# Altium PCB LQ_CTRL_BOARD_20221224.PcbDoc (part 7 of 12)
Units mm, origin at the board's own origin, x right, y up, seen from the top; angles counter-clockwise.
Board outline 260 x 142 mm, 6 copper layers (Top Layer, Mid-Layer 1, Mid-Layer 2, Mid-Layer 3, Mid-Layer 4, Bottom Layer); 1105 components, 1039 nets, 3898 pads, 1277 vias.
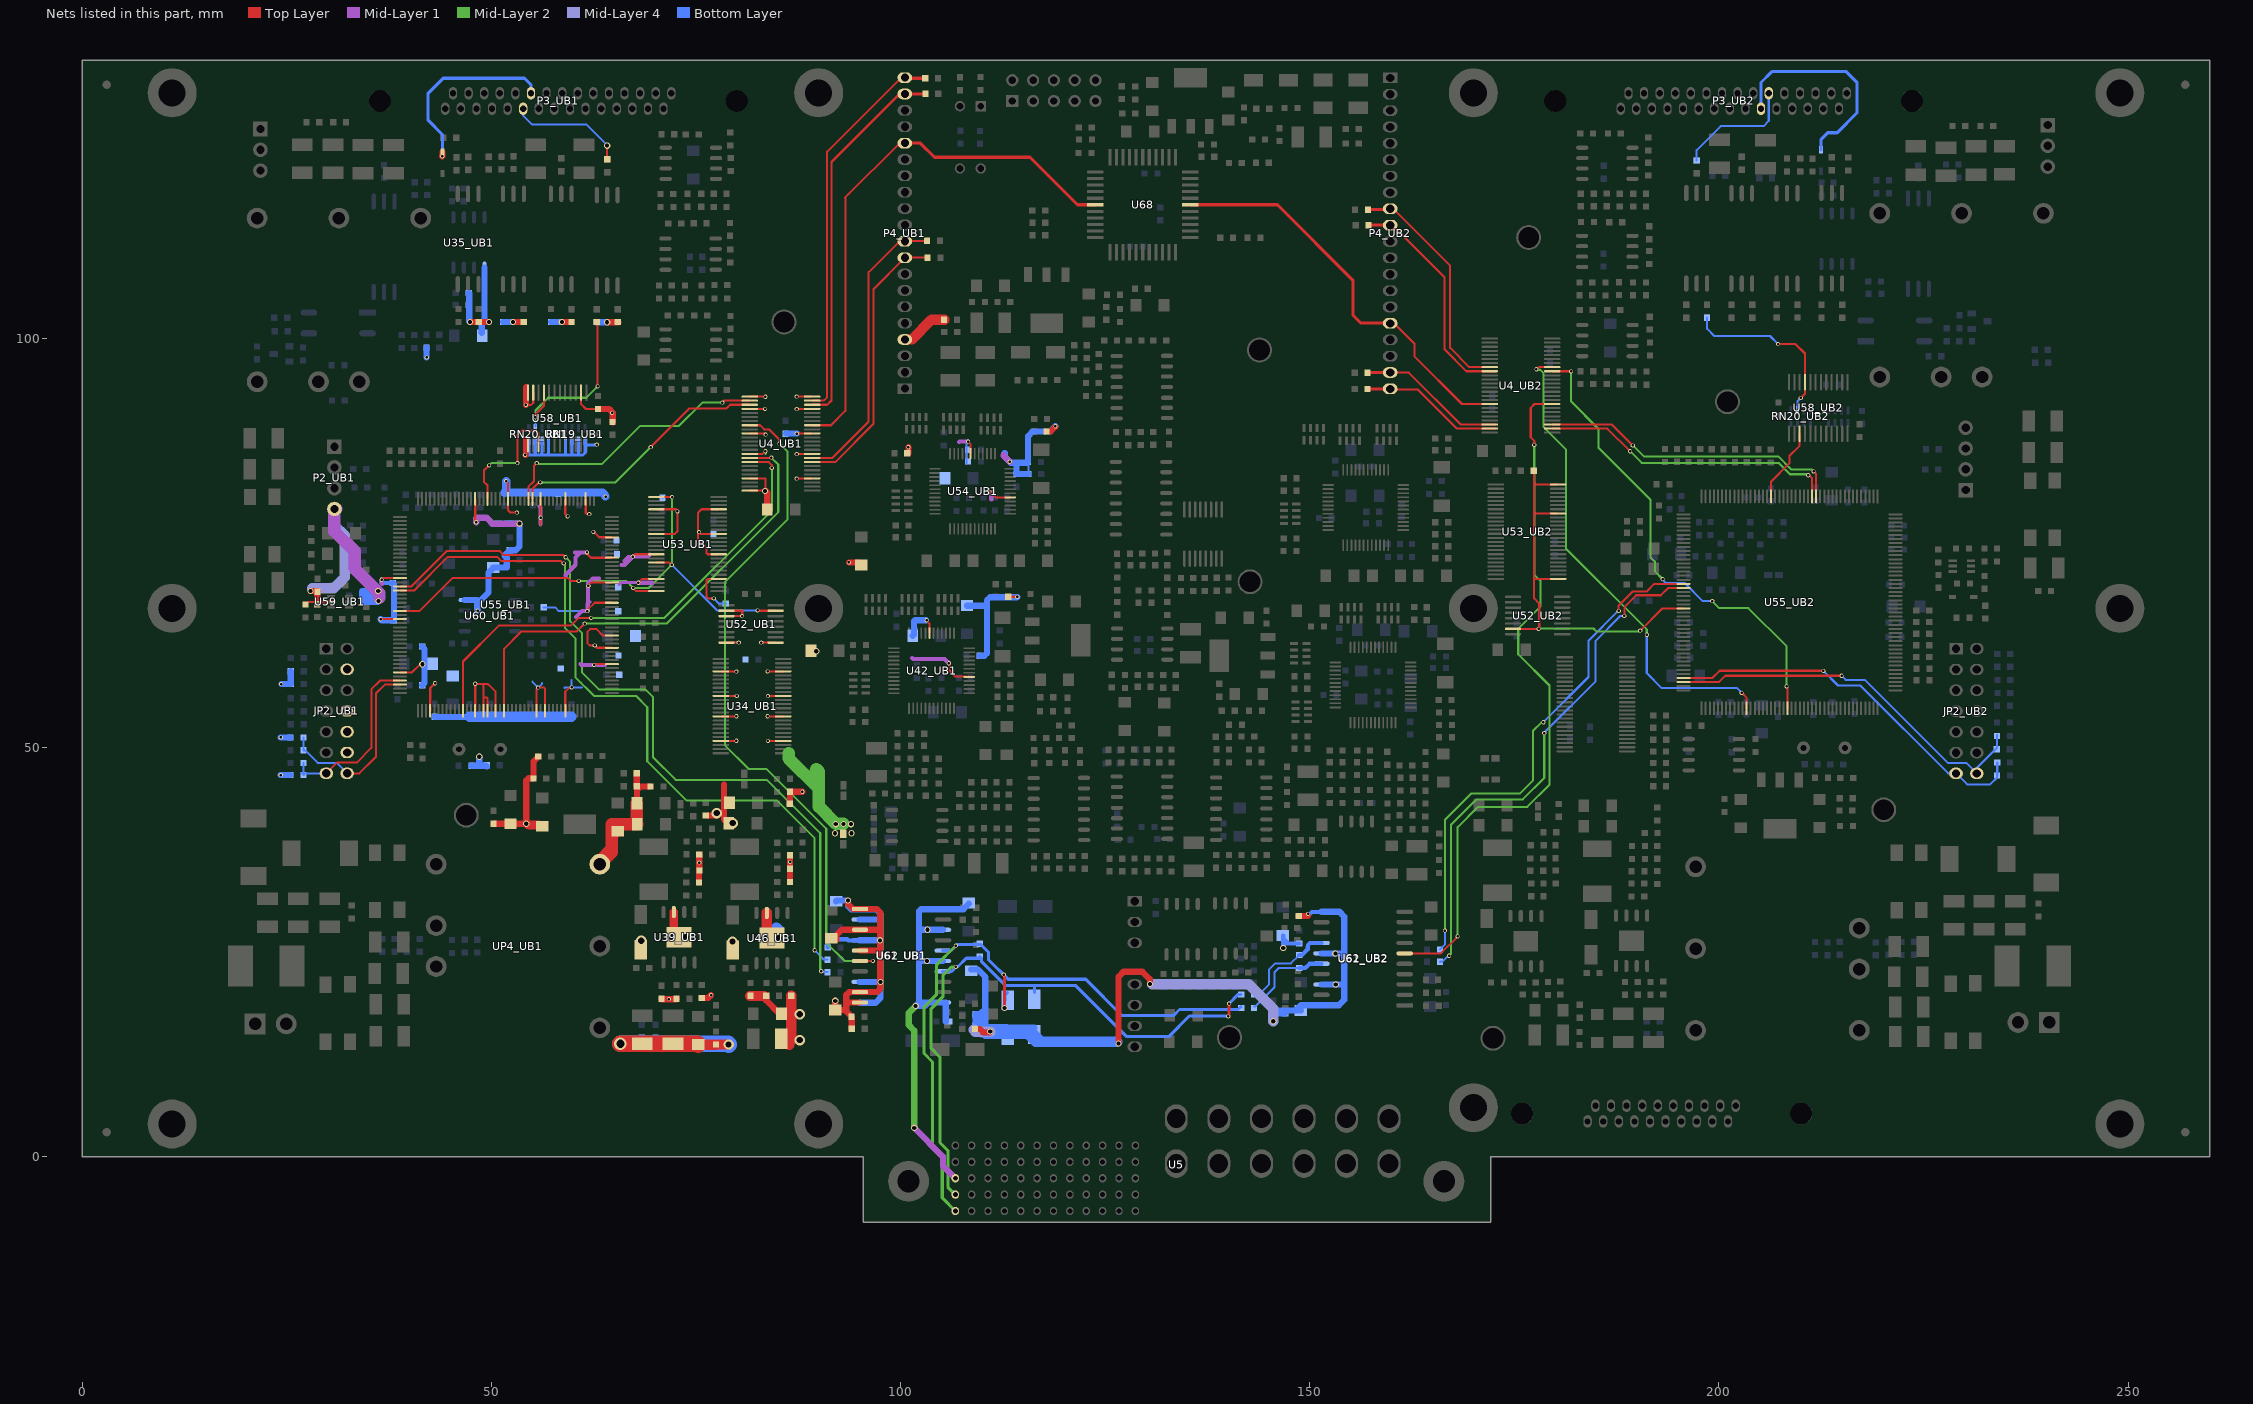
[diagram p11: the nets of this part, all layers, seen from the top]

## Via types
v1: diameter 0.508, hole 0.305, Top Layer to Bottom Layer, 845 vias
v2: diameter 0.762, hole 0.508, Top Layer to Bottom Layer, 317 vias
v3: diameter 1.27, hole 0.762, Top Layer to Bottom Layer, 77 vias
v4: diameter 2.032, hole 1.524, Top Layer to Bottom Layer, 15 vias
v5: diameter 2.032, hole 1.27, Top Layer to Bottom Layer, 11 vias
v6: diameter 1.27, hole 0.711, Top Layer to Bottom Layer, 8 vias
v7: diameter 2.54, hole 1.778, Top Layer to Bottom Layer, 3 vias
v8: diameter 1.524, hole 1.016, Top Layer to Bottom Layer, 1 vias

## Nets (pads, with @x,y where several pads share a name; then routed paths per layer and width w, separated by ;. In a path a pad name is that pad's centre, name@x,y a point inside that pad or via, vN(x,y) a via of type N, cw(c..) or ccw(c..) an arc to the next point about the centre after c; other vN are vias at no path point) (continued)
BRDC_CS_UB1: R313_UB1.1 U52_UB1.15 U53_UB1.25 U53_UB1.41 U53_UB1.48 U55_UB1.68 | length 67.9
  Top Layer w0.254: U55_UB1.68@38.84,66.691 41.24,66.691 45.288,70.739 59.334,70.739 59.715,70.358 v1(60.681,70.358) ; v1(67.335,69.494) 67.716,69.113 U53_UB1.48@69.367,69.113 ; U53_UB1.48@70.18,69.113 U53_UB1.48@70.993,69.113 ; U53_UB1.41@70.18,72.613 71.76,72.613 v1(72.06,72.314) ; U53_UB1.25@70.18,80.613 72.078,80.613 v1(72.085,80.606) ; v1(82.55,66.751) 82.88,66.751 ; 82.921,66.711 U52_UB1.15@84.74,66.711
  Mid-Layer 2 w0.254: v1(60.681,70.358) 66.472,70.358 v1(67.335,69.494) 69.24,69.494 v1(72.06,72.314) 72.06,76.479 72.085,76.505 v1(72.085,80.606)
  Bottom Layer w0.254: R313_UB1.1@70.917,80.518 71.005,80.606 v1(72.085,80.606) ; v1(72.06,72.314) 77.622,66.751 v1(82.55,66.751)
BRDC_CS_UB2: R313_UB2.1 U52_UB2.15 U53_UB2.25 U53_UB2.41 U53_UB2.48 U55_UB2.68 | length 50.5
  Top Layer w0.254: U52_UB2.15@174.848,64.506 177.993,64.506 178.054,64.567 178.054,67.589 177.419,68.224 177.419,70.587 ; R313_UB2.1@177.394,83.591 177.419,83.566 177.419,82.144 ; U53_UB2.25@180.365,70.618 177.451,70.618 177.419,70.587 ; U53_UB2.41@180.365,78.618 177.439,78.618 177.419,78.638 ; U53_UB2.48@180.365,82.118 177.444,82.118 177.419,82.144 ; v1(190.398,64.287) 193.107,66.996 ; 193.116,66.996 U55_UB2.68@195.685,66.996 ; 177.419,70.587 177.419,78.638 ; 177.419,78.638 177.419,82.144
  Mid-Layer 2 w0.254: v1(177.978,64.491) 178.029,64.541 184.683,64.541 185.039,64.186 190.398,64.186 v1(190.398,64.287)
CANGND_UB1: C11_UB1.2 C11_UB2.2 C410_UB1.2 C410_UB2.2 C411_UB1.2 C411_UB2.2 C412_UB1.2 C412_UB2.2 DR9.1 DR10.1 R367_UB1.1 R367_UB2.1 R371_UB1.1 R371_UB2.1 U5.C1 U61_UB1.11 U61_UB1.13 U61_UB1.16 U61_UB1.20 U61_UB2.11 U61_UB2.13 U61_UB2.16 U61_UB2.20 | length 169.2
  Top Layer w0.762: R371_UB1.1@109.118,15.621 109.682,15.621 110.114,15.189 110.871,15.189 v2(110.973,15.291) ; v2(126.644,13.843) 126.644,21.996 127.254,22.606 129.565,22.606 130.48,21.692 v2(130.48,21.107) ; R371_UB2.1@148.666,29.413 149.682,29.413 149.708,29.439 v1@149.809,29.439
  Mid-Layer 1 w0.762: v2(101.676,3.531) 105.181,0.025 105.181,-1.109 U5.C1@106.7,-2.627
  Mid-Layer 2 w0.762: v2(101.676,3.531) 101.676,15.418 101,16.094 101,17.561 v2(101.854,18.415)
  Mid-Layer 4 w1.27: 108.941,15.494 109.144,15.291 v2(110.973,15.291) ; v2@130.759,21.082 142.57,21.082 145.542,18.11 v2(145.542,16.561)
  Bottom Layer w0.508: v2@146.736,25.578 C11_UB2.2@146.736,27.051 C11_UB2.2@146.761,27.026 ; v2(146.761,25.502) v2@146.761,25.857 ; 147.726,26.06 R367_UB2.1@148.717,26.06 ; v1(149.809,29.667) 150.038,29.667 150.292,29.921 U61_UB2.20@151.449,29.921 ; v2@146.761,25.857 C11_UB2.2@146.761,27.026 ; v2@146.761,25.857 147.015,26.111 147.066,26.06 147.422,26.06 146.761,26.721 C11_UB2.2@146.761,27.026
  Bottom Layer w0.762: U61_UB1.16@105.161,23.927 102.286,23.927 102.26,23.952 ; U61_UB1.13@105.161,27.737 102.311,27.737 102.26,27.686 ; 105.537,16.535 105.537,18.847 U61_UB1.20@105.161,18.847 103.403,18.847 ; C11_UB1.2@108.356,30.912 107.696,30.251 U61_UB1.11@105.161,30.251 102.514,30.251 102.26,29.997 102.26,27.686 ; C411_UB1.2@108.636,22.885 109.449,22.885 110.363,21.971 110.363,17.851 ; C412_UB1.2@109.138,16.027 109.138,15.22 109.144,15.215 ; C412_UB1.2@109.164,16.053 C410_UB1.2@109.164,17.45 110.134,17.45 110.363,17.678 110.363,15.824 ; 110.261,15.189 110.363,15.291 110.363,15.824 ; DR9.1@116.357,15.748 113.055,15.748 112.979,15.824 110.363,15.824 ; v2@145.542,16.51 v2(145.542,16.561) 145.542,17.501 C412_UB2.2@145.567,17.526 ; C410_UB2.2@147.015,17.526 C412_UB2.2@145.567,17.526 ; C411_UB2.2@148.92,17.882 C411_UB2.2@148.299,17.882 ; U61_UB2.13@151.449,21.031 154.229,21.031 ; U61_UB2.16@151.449,24.841 154.203,24.841 154.229,24.867 ; U61_UB2.20@151.449,29.921 153.645,29.921 154.229,29.337 154.229,24.867 ; 102.26,18.821 102.286,18.847 103.403,18.847 ; 102.26,18.821 102.26,23.952 ; 102.26,18.821 v2(101.854,18.415) 102.972,18.415 103.403,18.847 ; 102.26,23.952 102.26,27.686 ; C412_UB2.2@145.567,17.526 145.923,17.882 C411_UB2.2@148.299,17.882 ; C411_UB2.2@148.299,17.882 148.934,18.517 U61_UB2.11@151.449,18.517 153.568,18.517 154.229,19.177 154.229,21.031 ; 154.229,21.031 154.229,24.867
  Bottom Layer w1.27: 110.134,17.45 109.823,17.139 109.823,15.316 109.95,15.189 110.261,15.189 110.414,15.037 115.545,15.037 116.51,14.072 117.221,14.072 ; DR9.1@116.357,14.935 117.221,14.072 ; v2@126.467,14.072 117.221,14.072
  other v2: 153.187,21.031 103.226,23.927 153.137,24.841 103.302,27.737
CANH_UB1: DR9.2 R370_UB1.1 R413.2 U5.B1 U61_UB1.17 | length 76.4
  Top Layer w0.381: v1(140.056,17.145) 140.157,17.247 v1(140.157,18.72)
  Mid-Layer 2 w0.381: U5.B1@106.7,-4.627 105.791,-3.718 105.791,0.762 104.826,1.727 104.826,12.167 103.746,13.246 103.746,18.098 105.181,19.533 105.181,22.149 106.223,23.19 v1(106.782,23.19)
  Bottom Layer w0.381: U61_UB1.17@105.161,22.657 106.248,22.657 v1(106.782,23.19) 106.832,23.241 107.036,23.241 108.052,24.257 ; 108.458,24.257 108.052,24.257 ; R370_UB1.1@109.677,24.46 R370_UB1.1@109.88,24.257 ; DR9.2@116.357,20.048 116.357,20.803 ; v1(140.056,17.145) 140.005,17.196 135.306,17.196 132.791,14.681 127.66,14.681 121.437,20.904 112.852,20.904 109.88,23.876 R370_UB1.1@109.88,24.257 ; v1(140.157,18.72) 141.275,19.837 R413.2@141.63,19.837 ; 108.052,24.257 R370_UB1.1@109.88,24.257
CANH_UB2: R370_UB2.1 R413.1 U61_UB2.17 | length 12.2
  Bottom Layer w0.254: R413.1@143.205,19.837 143.815,19.837 145.009,21.031 145.009,22.86 145.771,23.622 147.701,23.622 R370_UB2.1@148.717,24.638
  Bottom Layer w0.508: R370_UB2.1@148.717,24.638 149.047,24.638 149.758,25.349 149.758,25.654 149.784,25.679 149.784,25.857 150.038,26.111 U61_UB2.17@151.449,26.111
CANL_UB1: DR10.2 R370_UB1.2 R415.2 U5.A1 U61_UB1.15 | length 82.3
  Top Layer w0.381: v1(112.624,22.25) 112.725,22.149 v2(112.725,18.161)
  Mid-Layer 2 w0.381: U5.A1@106.7,-6.627 105.105,-5.032 105.105,0.102 103.911,1.295 103.911,11.582 102.87,12.624 102.87,18.263 104.383,19.776 104.383,23.408 v1(106.782,25.806)
  Bottom Layer w0.381: U61_UB1.15@105.161,25.197 106.223,25.197 106.959,25.933 109.83,25.933 110.744,25.019 110.744,24.105 113.157,21.692 122.631,21.692 127.076,17.247 133.35,17.247 134.087,17.983 141.249,17.983 R415.2@141.63,18.364 ; DR10.2@112.751,19.05 112.751,19.743 DR10.2@113.055,20.048
CANL_UB2: R370_UB2.2 R415.1 U61_UB2.15 | length 11.5
  Bottom Layer w0.254: R415.1@143.205,18.364 143.358,18.364 145.694,20.701 145.694,22.555 146.202,23.063 R370_UB2.2@148.717,23.063
  Bottom Layer w0.508: R370_UB2.2@148.717,23.063 149.454,23.063 149.962,23.571 U61_UB2.15@151.449,23.571
CANRXA_UB1: R368_UB1.2 U55_UB1.62 | length 98.9
  Top Layer w0.254: U55_UB1.62@38.84,69.691 40.252,69.691 44.577,74.016 51.02,74.016 51.528,73.508 58.826,73.508 v1(59.08,73.254)
  Mid-Layer 2 w0.254: v1@59.068,73.292 59.639,72.72 59.639,65.43 ; 59.639,67.183 59.639,65.43 ; 70.18,48.412 69.748,48.844 ; v1(90.322,22.657) 90.195,22.784 90.195,39.522 83.668,46.05 72.542,46.05 69.748,48.844 ; 59.639,65.43 61.062,64.008 61.062,59.182 63.144,57.099 68.834,57.099 69.748,56.185 69.748,48.844
  Bottom Layer w0.254: v1(90.322,22.657) 90.424,22.555 R368_UB1.2@91.084,22.555
CANRXA_UB2: R368_UB2.2 U55_UB2.62 | length 63.8
  Top Layer w0.254: v1(187.757,66.7) 187.757,67.361 189.459,69.063 191.186,69.063 192.119,69.996 U55_UB2.62@195.685,69.996
  Mid-Layer 2 w0.254: v1@166.497,27.61 v1(166.522,27.635) 166.522,41.148 169.774,44.399 175.717,44.399 177.267,45.949 177.267,52.019 178.346,53.099 v1(178.549,53.099)
  Bottom Layer w0.254: R368_UB2.2@165.913,25.298 166.522,25.908 v1(166.522,27.635) ; v1(178.549,53.099) 184.074,58.623 184.074,63.068 187.706,66.7 v1(187.757,66.7)
CANTXA_UB1: R369_UB1.2 U55_UB1.63 | length 94.5
  Top Layer w0.254: U55_UB1.63@38.84,69.191 40.591,69.191 44.704,73.304 50.724,73.304 51.232,72.796 58.496,72.796 v1@58.826,72.466
  Mid-Layer 2 w0.254: v1@58.826,72.466 59.03,72.263 59.03,64.592 ; 59.03,64.618 59.03,64.592 ; 60.935,57.937 60.274,58.598 ; v1@89.51,25.248 89.51,38.913 84.887,43.536 73.838,43.536 69.063,48.311 69.063,54.94 67.701,56.301 62.571,56.301 60.274,58.598 ; 59.03,64.592 60.274,63.348 60.274,58.598
  Bottom Layer w0.254: v1(89.51,25.222) 90.653,24.079 R369_UB1.2@91.084,24.079
  other v1: 58.852,72.492
CANTXA_UB2: R369_UB2.2 U55_UB2.63 | length 64.7
  Top Layer w0.254: v1(188.443,66.091) 188.443,67.14 189.908,68.605 192.913,68.605 193.803,69.496 U55_UB2.63@195.685,69.496
  Mid-Layer 2 w0.254: v1(167.03,24.562) 167.259,24.79 167.259,40.538 170.383,43.663 176.047,43.663 178.664,46.279 v1(178.664,51.765)
  Bottom Layer w0.254: R369_UB2.2@165.913,23.825 166.192,23.825 166.929,24.562 v1(167.03,24.562) ; v1(178.664,51.765) 178.638,51.791 184.937,58.09 184.937,63.043 187.985,66.091 v1(188.443,66.091)
EMU0_UB1: C375_UB1.1 JP2_UB1.13 R311_UB1.1 U55_UB1.85 | length 22.7
  Top Layer w0.254: JP2_UB1.13@29.845,46.849 31.142,48.146 33.541,48.146 35.357,49.962 35.357,57.099 36.449,58.191 U55_UB1.85@38.84,58.191
  Bottom Layer w0.254: C375_UB1.1@26.809,46.849 C375_UB1.1@27.266,46.849 ; R311_UB1.1@27.051,48.108 C375_UB1.1@27.051,46.634 C375_UB1.1@27.266,46.849 ; JP2_UB1.13@29.845,46.849 C375_UB1.1@27.266,46.849
EMU0_UB2: C375_UB2.1 JP2_UB2.13 R311_UB2.1 U55_UB2.85 | length 46.6
  Top Layer w0.254: U55_UB2.85@195.685,58.496 199.212,58.496 200.101,59.385 v1@212.801,59.385
  Bottom Layer w0.254: v1(212.776,59.36) 214.554,57.582 217.272,57.582 228.016,46.838 JP2_UB2.13@228.981,46.838 230.327,45.491 233.147,45.491 233.985,46.33 233.985,46.646 234.01,46.672 R311_UB2.1@234.01,48.17
EMU1_UB1: C376_UB1.1 JP2_UB1.14 R312_UB1.2 U55_UB1.86 | length 23.5
  Top Layer w0.254: JP2_UB1.14@32.385,46.849 33.87,46.849 35.916,48.895 35.916,56.617 36.99,57.691 U55_UB1.86@38.84,57.691
  Bottom Layer w0.254: C376_UB1.1@27.051,51.232 R312_UB1.2@27.051,49.657 27.254,49.657 28.778,48.133 31.101,48.133 JP2_UB1.14@32.385,46.849
EMU1_UB2: C376_UB2.1 JP2_UB2.14 R312_UB2.2 U55_UB2.86 | length 46.6
  Top Layer w0.254: U55_UB2.86@195.685,57.996 200.007,57.996 200.787,58.776 214.723,58.776
  Bottom Layer w0.254: v1(214.986,58.776) 215.494,58.268 217.843,58.268 227.978,48.133 230.226,48.133 JP2_UB2.14@231.521,46.838 231.521,47.498 233.959,49.936 233.959,51.523 C376_UB2.1@233.985,51.548
EN_TXD_UB1: P4_UB1.16 U4_UB1.17 U68.6 | length 68
  Top Layer w0.254: U4_UB1.17@89.205,89.382 91.515,89.382 93.269,91.135 93.269,117.221 ; 93.218,117.17 93.269,117.221 ; 93.701,117.653 93.269,117.221 ; P4_UB1.16@100.533,123.853 99.901,123.853 93.269,117.221
  Top Layer w0.381: P4_UB1.16@100.533,123.853 102.436,123.853 104.165,122.123 115.824,122.123 121.627,116.32 U68.6@123.8,116.32
EN_TXD_UB2: P4_UB2.16 U4_UB2.17 U68.28 | length 50.9
  Top Layer w0.254: P4_UB2.16@159.842,101.572 160.581,101.572 162.789,99.365 162.789,97.79 168.605,91.973 U4_UB2.17@172.771,91.973
  Top Layer w0.381: U68.28@135.4,116.32 146.062,116.32 155.27,107.112 155.27,102.845 156.235,101.879 159.535,101.879 P4_UB2.16@159.842,101.572
EN_WK_UB1: R23_UB1.1 RN20_UB1.3 U58_UB1.9 | length 22.2
  Top Layer w0.254: v1(55.397,90.348) 55.397,90.703 56.426,91.732 U58_UB1.9@56.426,93.37 ; v1(62.997,94.132) R23_UB1.1@62.997,102.083
  Mid-Layer 2 w0.254: v1(55.397,90.348) 55.397,91.186 56.947,92.735 61.6,92.735 v1(62.997,94.132)
  Bottom Layer w0.254: RN20_UB1.3@55.378,89.256 55.378,90.329 v1(55.397,90.348)
EN_WK_UB2: R23_UB2.1 RN20_UB2.3 U58_UB2.9 | length 21.9
  Top Layer w0.254: v1(207.239,99.289) 207.264,99.314 209.347,99.314 210.519,98.141 U58_UB2.9@210.519,94.64 210.519,93.222 v1(210.007,92.71)
  Bottom Layer w0.254: R23_UB2.1@198.557,102.514 198.557,101.163 199.441,100.279 206.248,100.279 v1(207.239,99.289) ; RN20_UB2.3@209.607,91.211 209.607,92.31 v1(210.007,92.71)
EN_WORK_UB1: U55_UB1.27 U58_UB1.15 | length 15.8
  Top Layer w0.254: U55_UB1.27@49.54,80.391 49.54,82.057 49.098,82.499 49.098,83.845 v1(49.733,84.48) ; v1(53.188,84.76) 53.188,88.239 53.696,88.748 55.397,88.748 55.776,88.369 U58_UB1.15@55.776,87.07
  Mid-Layer 2 w0.254: v1(49.733,84.48) 50.013,84.76 v1(53.188,84.76)
EN_WORK_UB2: U55_UB2.27 U58_UB2.15 | length 9.1
  Top Layer w0.254: U55_UB2.27@206.385,80.696 206.385,82.509 208.61,84.734 208.61,85.432 208.636,85.458 208.636,85.648 209.869,86.882 ; 209.869,86.868 U58_UB2.15@209.869,88.34
EN_WRK_UB1: P3_UB1.6 R248_UB1.2 | length 14.4
  Top Layer w0.254: R248_UB1.2@64.166,121.869 v2@64.166,123.546
  Bottom Layer w0.254: P3_UB1.6@53.899,128.047 53.899,127.203 54.966,126.136 61.62,126.136 64.033,123.723 v2@64.338,123.723
  other v2: 64.16,123.546
EN_WRK_UB2: P3_UB2.6 R248_UB2.2 | length 15.5
  Bottom Layer w0.254: R248_UB2.2@197.287,121.742 197.287,122.992 200.228,125.933 205.461,125.933 206.096,126.568 P3_UB2.6@206.096,130.505
ENA_TXD_UB1: U4_UB1.32 U62_UB1.6 | length 84
  Top Layer w0.254: U4_UB1.32@81.585,89.382 82.856,89.382 83.356,88.882 83.94,88.882 85.217,87.605 v1(85.217,87.147) ; U62_UB1.6@95.052,23.927 v1(96.622,23.927)
  Mid-Layer 2 w0.254: v1(85.217,87.147) 86.208,86.157 86.208,77.876 78.537,70.206 78.537,50.292 81.432,47.396 83.617,47.396 90.932,40.081 90.932,26.152 93.157,23.927 v1(96.622,23.927)
ENA_TXD_UB2: U4_UB2.32 U62_UB2.6 | length 86.2
  Top Layer w0.254: U62_UB2.6@161.615,24.841 166.014,24.841 168.072,26.899 v1(168.072,26.924) ; v1(177.444,86.97) 177.444,87.477 177.013,87.909 177.013,91.511 177.476,91.974 U4_UB2.32@179.629,91.974
  Top Layer w0.381: U62_UB2.6@161.615,24.841 U62_UB2.6@161.691,24.917
  Mid-Layer 2 w0.254: v1(168.072,26.924) 168.072,40.259 170.561,42.748 176.581,42.748 179.299,45.466 179.299,57.582 175.489,61.392 175.489,64.516 178.181,67.208 178.181,70.383 177.444,71.12 v1(177.444,86.97)
ET_IO_IN1_UB1: U4_UB1.27 U55_UB1.16 | length 32.1
  Top Layer w0.254: U55_UB1.16@55.04,80.391 55.04,81.622 55.74,82.321 55.982,82.321 v1(55.982,82.398) ; v1(69.494,86.716) 74.219,91.44 78.74,91.44 79.182,91.882 U4_UB1.27@81.585,91.882
  Mid-Layer 2 w0.254: v1(55.982,82.398) 65.176,82.398 v1(69.494,86.716)
ET_IO_IN1_UB2: U4_UB2.27 U55_UB2.16 | length 37.6
  Top Layer w0.254: U4_UB2.27@179.629,89.474 186.917,89.474 189.509,86.882 189.509,86.893 v1(189.484,86.919) ; v1(211.582,83.744) 211.885,83.441 U55_UB2.16@211.885,80.696
  Mid-Layer 2 w0.254: v1(189.484,86.919) 190.83,85.573 207.239,85.573 208.839,83.972 211.207,83.972 211.353,83.972 v1(211.582,83.744)
ET_IO_IN2_UB1: U4_UB1.26 U55_UB1.17 | length 34.1
  Top Layer w0.254: U55_UB1.17@54.54,80.391 54.54,81.845 55.22,82.525 55.22,84.43 v1(55.55,84.76) ; v1(78.232,92.151) 78.462,92.382 U4_UB1.26@81.585,92.382
  Mid-Layer 2 w0.254: v1(55.55,84.76) 55.651,84.658 63.551,84.658 68.192,89.3 72.942,89.3 75.794,92.151 v1(78.232,92.151)
ET_IO_IN2_UB2: U4_UB2.26 U55_UB2.17 | length 36.5
  Top Layer w0.254: U4_UB2.26@179.629,88.974 186.362,88.974 189.154,86.182 v1(189.154,86.208) ; v1@210.998,83.337 210.998,83.299 211.385,82.911 U55_UB2.17@211.385,80.696
  Mid-Layer 2 w0.254: v1@189.179,86.182 190.576,84.785 207.289,84.785 208.686,83.388 210.642,83.388 210.795,83.388 v1(210.922,83.261)
ET_IO_OUT1_UB1: U4_UB1.41 U55_UB1.100 | length 59.8
  Top Layer w0.254: U55_UB1.100@46.54,54.491 46.54,60.51 50.927,64.897 59.726,64.897 60.666,65.837 v1(62.205,65.837) ; U4_UB1.41@81.585,84.882 83.901,84.882 84.277,84.506 v1(84.277,84.176)
  Mid-Layer 2 w0.254: v1(62.205,65.837) 71.171,65.837 84.277,78.943 v1(84.277,84.176)
ET_IO_OUT1_UB2: U4_UB2.41 U55_UB2.100 | length 59.8
  Top Layer w0.254: v1(177.698,96.215) 177.788,96.215 178.047,96.474 U4_UB2.41@179.629,96.474 ; v1(202.768,56.667) 202.819,56.667 203.385,56.101 U55_UB2.100@203.385,54.796
  Mid-Layer 2 w0.254: v1(177.698,96.215) 177.749,96.164 178.156,96.164 178.587,95.733 178.587,89.154 181.305,86.436 181.305,74.32 191.186,64.44 v1@191.186,63.805
  Bottom Layer w0.254: v1@191.186,63.805 191.186,59.106 193.04,57.252 202.235,57.252 202.819,56.667 v1(202.768,56.667)
  other v1: 191.211,63.779
ET_IO_OUT2_UB1: U4_UB1.40 U55_UB1.110 | length 57.7
  Top Layer w0.254: U55_UB1.110@51.54,54.491 51.54,62.03 53.696,64.186 60.452,64.186 v1(61.417,65.151) ; U4_UB1.40@81.585,85.382 84.188,85.382 v1(84.226,85.42)
  Mid-Layer 2 w0.254: v1(61.417,65.151) 71.45,65.151 85.065,78.765 85.065,84.582 v1(84.226,85.42)
ET_IO_OUT2_UB2: U4_UB2.40 U55_UB2.110 | length 58.6
  Top Layer w0.254: U4_UB2.40@179.629,95.974 181.927,95.974 v1(181.94,95.961) ; v1(208.28,57.474) 208.385,57.369 U55_UB2.110@208.385,54.796
  Mid-Layer 2 w0.254: v1(181.94,95.961) 181.94,92.278 185.293,88.925 185.293,86.639 191.643,80.289 191.643,73.203 191.694,73.203 192.176,72.72 192.176,71.526 v1(193.116,70.587) ; v1(199.187,67.894) 200.05,67.031 203.606,67.031 208.28,62.357 v1(208.28,57.474)
  Bottom Layer w0.254: v1(193.116,70.587) 193.116,70.561 193.091,70.536 193.523,70.104 195.809,70.104 198.018,67.894 v1(199.187,67.894)
EXT_IO_IN1_UB1: P4_UB1.19 R391.1 U4_UB1.22 | length 46.9
  Top Layer w0.254: U4_UB1.22@89.205,91.882 91.043,91.882 91.567,92.405 91.567,121.539 ; 91.948,121.92 91.567,121.539 ; P4_UB1.19@100.533,129.853 99.881,129.853 91.567,121.539
  Top Layer w0.381: P4_UB1.19@100.533,129.853 102.76,129.853 R391.1@102.794,129.819
EXT_IO_IN1_UB2: P4_UB2.19 R432.1 U4_UB2.22 | length 18.4
  Top Layer w0.254: P4_UB2.19@159.605,95.809 162.128,95.809 168.463,89.474 U4_UB2.22@172.771,89.474
  Top Layer w0.381: R432.1@157.074,95.58 157.302,95.809 P4_UB2.19@159.605,95.809
EXT_IO_IN2_UB1: P4_UB1.20 R392.1 U4_UB1.23 | length 48
  Top Layer w0.254: U4_UB1.23@89.205,92.382 90.629,92.382 91.034,92.786 91.034,122.809 100.078,131.853 P4_UB1.20@100.533,131.853
  Top Layer w0.381: P4_UB1.20@100.533,131.853 100.611,131.775 R392.1@103.2,131.775
EXT_IO_IN2_UB2: P4_UB2.20 R433.1 U4_UB2.23 | length 17.8
  Top Layer w0.254: P4_UB2.20@160.022,93.751 163.22,93.751 167.997,88.974 U4_UB2.23@172.771,88.974
  Top Layer w0.381: R433.1@157.074,93.802 P4_UB2.20@159.793,93.802 ; P4_UB2.20@159.793,93.523 P4_UB2.20@160.022,93.751
EXT_IO_OUT1_UB1: P4_UB1.9 R393.1 U4_UB1.8 | length 34.1
  Top Layer w0.254: U4_UB1.8@89.205,84.882 92.008,84.882 96.698,89.571 96.698,106.018 P4_UB1.9@100.533,109.853 100.535,109.855 R393.1@103.302,109.855
EXT_IO_OUT1_UB2: P4_UB2.9 R434.1 U4_UB2.8 | length 29.6
  Top Layer w0.254: P4_UB2.9@160.146,115.876 167.157,108.864 167.157,98.831 169.514,96.474 U4_UB2.8@172.72,96.474
  Top Layer w0.381: R434.1@157.124,115.722 P4_UB2.9@159.84,115.722 ; P4_UB2.9@159.84,115.57 P4_UB2.9@160.146,115.876
EXT_IO_OUT2_UB1: P4_UB1.10 R394.1 U4_UB1.9 | length 35.7
  Top Layer w0.254: U4_UB1.9@89.205,85.382 91.655,85.382 96.114,89.84 96.114,108.077 99.89,111.853 P4_UB1.10@100.533,111.853 100.593,111.912 R394.1@103.251,111.912
EXT_IO_OUT2_UB2: P4_UB2.10 R436.1 U4_UB2.9 | length 28
  Top Layer w0.254: P4_UB2.10@159.842,113.572 160.367,113.572 166.472,107.467 166.472,98.654 169.151,95.974 U4_UB2.9@172.72,95.974
  Top Layer w0.381: R436.1@157.277,113.843 P4_UB2.10@159.876,113.843 ; P4_UB2.10@159.8,113.614 P4_UB2.10@159.842,113.572
FAULT_UB1: D16_UB1.2 P3_UB1.21 | length 23.6
  Top Layer w0.762: v1(44.018,122.25) D16_UB1.2@44.044,122.742
  Bottom Layer w0.381: v1@44.044,122.25 44.044,124.892 42.291,126.644 42.291,129.946 44.12,131.775 54.051,131.775 54.851,130.976 P3_UB1.21@54.851,129.952
FAULT_UB2: D16_UB2.2 P3_UB2.21 | length 29.5
  Bottom Layer w0.381: P3_UB2.21@205.146,128.047 205.146,131.257 206.477,132.588 ; 209.194,132.588 206.477,132.588 ; D16_UB2.2@212.496,123.021 212.496,124.307 213.309,125.12 214.452,125.12 216.865,127.533 216.865,131.293 215.57,132.588 206.477,132.588
GND_UB1: C10_UB1.2 C16_UB1.2 C17_UB1.2 C228_UB1.2 C233_UB1.2 C234_UB1.1 C235_UB1.1 C237_UB1.1 C238_UB1.1 C254_UB1.2 C255_UB1.2 C263_UB1.2 C264_UB1.1 C265_UB1.2 C266_UB1.1 C273_UB1.1 C274_UB1.1 C291_UB1.2 C292_UB1.2 C294_UB1.2 C295_UB1.1 C296_UB1.1 C297_UB1.1 C309_UB1.2 C310_UB1.1 C313_UB1.2 C314_UB1.2 C315_UB1.2 C316_UB1.2 C317_UB1.2 C318_UB1.2 C320_UB1.2 C321_UB1.2 C322_UB1.1 C323_UB1.1 C331_UB1.1 C332_UB1.1 C333_UB1.1 C334_UB1.1 C335_UB1.1 C336_UB1.1 C337_UB1.1 C338_UB1.1 C339_UB1.1 C340_UB1.1 C341_UB1.1 C342_UB1.1 C346_UB1.1 C347_UB1.1 C348_UB1.1 C349_UB1.1 C350_UB1.1 C351_UB1.1 C352_UB1.1 C353_UB1.1 C356_UB1.2 C357_UB1.2 C358_UB1.2 C359_UB1.2 C366_UB1.1 C367_UB1.2 C368_UB1.1 C375_UB1.2 C376_UB1.2 C383_UB1.2 C384_UB1.1 C385_UB1.2 C386_UB1.2 C387_UB1.2 C388_UB1.2 C390_UB1.1 C391_UB1.1 C401_UB1.2 C402_UB1.2 C403_UB1.2 C404_UB1.2 C405_UB1.1 C406_UB1.2 C407_UB1.2 C408_UB1.1 C409_UB1.2 C413_UB1.2 C414_UB1.2 C415_UB1.2 C416_UB1.2 C417_UB1.2 C418_UB1.2 C419_UB1.2 D20_UB1.1 D22_UB1.1 JP2_UB1.4 JP2_UB1.8 JP2_UB1.10 JP2_UB1.12 P2_UB1.4 P4_UB1.4 R1.1 R27_UB1.1 R210_UB1.1 R226_UB1.1 R227_UB1.1 R231_UB1.2 R234_UB1.2 R240_UB1.1 R241_UB1.1 R242_UB1.1 R243_UB1.2 R245_UB1.1 R247_UB1.1 R253_UB1.1 R254_UB1.1 R255_UB1.1 R262_UB1.2 R273_UB1.1 R274_UB1.2 R276_UB1.1 R289_UB1.1 R294_UB1.1 R296_UB1.2 R299_UB1.1 R302_UB1.1 R310_UB1.1 R359_UB1.2 R364_UB1.2 RN19_UB1.2 RN19_UB1.4 RN19_UB1.6 RN19_UB1.8 RN20_UB1.2 RN20_UB1.4 RN20_UB1.6 RN20_UB1.8 U4_UB1.4 U4_UB1.10 U4_UB1.15 U4_UB1.21 U4_UB1.24 U4_UB1.25 U4_UB1.28 U4_UB1.34 U4_UB1.39 U4_UB1.45 U4_UB1.48 U34_UB1.4 U34_UB1.10 U34_UB1.15 U34_UB1.21 U34_UB1.28 U34_UB1.34 U34_UB1.39 U34_UB1.45 U35_UB1.5 U39_UB1.7 U39_UB1.9 U42_UB1.5 U42_UB1.19 U46_UB1.7 U46_UB1.9 U52_UB1.2 U52_UB1.3 U52_UB1.8 U52_UB1.9 U53_UB1.4 U53_UB1.10 U53_UB1.15 U53_UB1.21 U53_UB1.28 U53_UB1.34 U53_UB1.39 U53_UB1.45 U54_UB1.5 U54_UB1.19 U55_UB1.3 U55_UB1.8 U55_UB1.14 U55_UB1.22 U55_UB1.30 U55_UB1.60 U55_UB1.70 U55_UB1.83 U55_UB1.92 U55_UB1.103 U55_UB1.105 U55_UB1.106 U55_UB1.108 U55_UB1.118 U55_UB1.120 U55_UB1.125 U55_UB1.140 U55_UB1.144 U55_UB1.147 U55_UB1.155 U55_UB1.160 U55_UB1.166 U55_UB1.171 U58_UB1.2 U58_UB1.11 U58_UB1.12 U58_UB1.13 U59_UB1.2 U60_UB1.4 U61_UB1.1 U61_UB1.3 U61_UB1.7 U61_UB1.9 U61_UB1.10 U62_UB1.1 U62_UB1.3 U62_UB1.5 U62_UB1.9 U62_UB1.10 UP4_UB1.5 | length 628.4
  Top Layer w0.254: C409_UB1.2@27.305,67.462 27.646,67.803 28.727,67.803 R359_UB1.2@28.727,67.513 ; v1@36.468,65.691 U55_UB1.70@38.84,65.691 ; v1(36.601,70.51) 36.601,70.536 36.757,70.691 U55_UB1.60@38.84,70.691 ; U55_UB1.83@38.84,59.191 40.319,59.191 41.3,60.173 v2(41.58,60.173) ; U55_UB1.92@42.54,54.491 42.54,57.272 v1(43.129,57.861) ; U55_UB1.103@48.04,54.491 v1(48.04,57.785) 48.844,57.785 ; v1@48.04,77.521 U55_UB1.30@48.04,80.391 ; U55_UB1.105@49.04,54.491 49.04,56.109 ; U55_UB1.106@49.54,54.491 49.54,56.022 49.428,56.134 49.066,56.134 49.04,56.109 ; 49.54,57.718 49.474,57.785 ; U55_UB1.108@50.54,54.491 50.54,56.82 49.575,57.785 49.474,57.785 ; v1(51.816,82.55) 51.816,82.56 52.04,82.336 U55_UB1.22@52.04,80.391 52.04,78.973 52.299,78.715 v1(53.137,78.715) ; v1(54.229,91.872) 54.864,91.872 55.126,92.134 U58_UB1.11@55.126,93.37 ; U55_UB1.118@55.54,54.491 55.54,57.14 v1(55.728,57.328) 56.439,57.328 56.54,57.226 U55_UB1.120@56.54,54.491 ; 56.032,77.191 v1(56.032,78.08) 56.032,80.383 U55_UB1.14@56.04,80.391 ; U55_UB1.125@59.04,54.491 59.04,56.805 ; 59.04,56.821 59.04,56.805 ; U55_UB1.8@59.04,80.391 59.04,78.526 v1(59.334,78.232) ; v1(59.817,57.353) 59.588,57.353 59.04,56.805 ; U58_UB1.2@60.976,93.37 60.976,91.958 61.57,91.364 C405_UB1.1@63.043,91.364 ; U55_UB1.3@61.54,80.391 61.54,78.668 61.677,78.531 v1(61.976,78.531) ; v1@61.697,73.965 v1(61.697,73.838) 61.697,73.685 62.191,73.191 U55_UB1.166@64.74,73.191 ; v1(61.747,66.675) 61.747,66.814 62.625,67.691 63.144,67.691 ; v1@61.798,69.774 62.215,70.191 U55_UB1.160@64.74,70.191 ; v1(62.484,76.352) 62.535,76.352 63.196,75.691 U55_UB1.171@64.74,75.691 ; v1(62.56,60.096) 62.655,60.191 U55_UB1.140@64.74,60.191 ; 62.814,67.691 63.144,67.691 ; U55_UB1.144@64.74,62.191 62.929,62.191 v1(62.636,62.484) 62.027,62.484 61.747,62.763 61.747,64.135 62.078,64.465 62.865,64.465 63.639,63.691 U55_UB1.147@64.74,63.691 ; U55_UB1.155@64.74,67.691 63.144,67.691 ; v1(67.285,73.33) 67.568,73.613 U53_UB1.39@70.18,73.613 ; v1(67.97,70.129) 68.454,70.613 U53_UB1.45@70.18,70.613 ; U53_UB1.34@70.18,76.113 72.43,76.113 72.771,76.454 72.771,78.918 72.575,79.113 U53_UB1.28@70.18,79.113 ; v1(77.191,68.224) 76.505,68.224 76.302,68.428 76.302,70.434 76.481,70.613 U53_UB1.4@77.8,70.613 ; U53_UB1.10@77.8,73.613 76.44,73.613 76.276,73.777 76.276,74.447 75.26,75.463 v1@75.26,76.36 ; U53_UB1.15@77.8,76.113 75.507,76.113 v1@75.26,76.36 ; U53_UB1.21@77.8,79.113 75.684,79.113 75.26,78.689 v1@75.26,76.36 ; U34_UB1.45@78.054,50.801 79.935,50.801 v1(79.959,50.825) ; U34_UB1.39@78.054,53.801 79.938,53.801 v1(79.959,53.823) ; U34_UB1.34@78.054,56.301 v1(79.985,56.301) ; U34_UB1.28@78.054,59.301 79.941,59.301 v1(79.959,59.284) ; U52_UB1.8@78.74,62.811 80.235,62.811 v1(80.239,62.814) ; U52_UB1.3@78.74,66.061 v1(80.64,66.061) 80.67,66.091 80.67,66.726 ; U52_UB1.2@78.74,66.711 80.655,66.711 80.67,66.726 ; 80.696,66.751 80.67,66.726 ; U4_UB1.48@81.585,81.382 83.515,81.382 83.515,82.855 83.488,82.882 U4_UB1.45@81.585,82.882 ; U4_UB1.39@81.585,85.882 83.164,85.882 v1(83.49,86.208) ; U4_UB1.34@81.585,88.382 83.479,88.382 v1@83.515,88.417 ; U4_UB1.28@81.585,91.382 v1(83.464,91.382) ; U4_UB1.25@81.585,92.882 83.471,92.882 v1(83.49,92.862) ; v1(82.982,62.814) 84.737,62.814 U52_UB1.9@84.74,62.811 ; v1(83.769,53.823) 83.79,53.801 U34_UB1.10@85.674,53.801 ; v1(83.769,59.301) U34_UB1.21@85.674,59.301 ; v1(83.795,50.8) 83.796,50.801 U34_UB1.4@85.674,50.801 ; v1(83.795,56.286) 83.81,56.301 U34_UB1.15@85.674,56.301 ; v1(87.3,82.855) 87.327,82.882 U4_UB1.4@89.205,82.882 ; v1(87.3,92.882) 87.3,92.888 87.306,92.882 U4_UB1.24@89.205,92.882 ; v1(87.325,85.852) 87.351,85.852 87.38,85.882 U4_UB1.10@89.205,85.882 ; v1(87.325,88.367) 87.34,88.382 U4_UB1.15@89.205,88.382 ; v1(87.325,91.364) 87.307,91.382 U4_UB1.21@89.205,91.382 ; v1(103.2,65.557) 103.2,65.481 103.549,65.133 U42_UB1.19@103.549,63.985 ; v1(105.918,60.301) 105.994,60.225 105.994,59.411 106.727,58.678 108.356,58.678 U42_UB1.5@108.399,58.635 ; v1(108.255,87.376) 108.563,87.068 U54_UB1.19@108.563,85.91 ; v1@111.1,81.661 v1(111.1,81.534) 111.1,81.128 111.667,80.56 U54_UB1.5@113.413,80.56 ; R255_UB1.1@113.172,68.428 114.249,68.428 v1(114.275,68.402) ; 48.844,57.785 49.474,57.785 ; 48.844,57.785 49.04,57.589 49.04,56.109
  Top Layer w0.508: R359_UB1.2@28.727,67.803 U59_UB1.2@30.41,67.803
  Top Layer w0.762: v2@27.965,69.139 C407_UB1.2@28.804,69.139 ; R359_UB1.2@28.727,67.803 C407_UB1.2@28.727,69.037 ; v2(47.386,102.006) R253_UB1.1@48.463,102.006 v2(49.733,102.006) ; C331_UB1.1@50.267,40.691 C359_UB1.2@52.349,40.691 v2(54.28,40.691) ; v2(52.654,102.006) R226_UB1.1@53.98,102.006 ; v1@54.178,85.75 54.229,85.801 54.229,87.655 ; v1(54.229,91.872) 54.229,94.024 ; R289_UB1.1@55.753,48.895 55.143,48.285 C320_UB1.2@55.143,46.228 55.118,46.228 55.093,46.253 54.559,46.253 54.28,45.974 v2(54.28,40.691) ; C313_UB1.2@56.21,40.386 C313_UB1.2@56.159,40.335 ; v2(58.623,101.981) R240_UB1.1@59.817,101.981 ; C405_UB1.1@63.043,91.364 64.389,91.364 64.846,90.907 C406_UB1.2@64.846,89.713 ; v2(64.16,101.956) R247_UB1.1@65.537,101.956 ; C321_UB1.2@67.767,45.263 R294_UB1.1@67.767,46.863 ; C255_UB1.2@67.793,43.18 67.793,44.806 68.224,45.237 C416_UB1.2@69.469,45.237 ; C264_UB1.1@70.79,19.253 v1(71.704,19.253) 72.593,19.253 R243_UB1.2@72.644,19.304 ; U39_UB1.9@72.314,27.432 U39_UB1.9@72.923,26.822 ; C263_UB1.2@75.311,13.716 75.59,13.437 R210_UB1.1@77.445,13.437 ; C274_UB1.1@75.387,33.528 75.387,35.25 75.418,35.281 R242_UB1.1@75.418,36.932 ; C273_UB1.1@75.717,19.406 76.505,19.406 v1(76.86,19.761) ; R234_UB1.2@76.429,41.681 77.495,41.681 v3@77.47,41.656 ; 78.435,45.441 78.435,41.25 C291_UB1.2@78.918,40.767 ; v2@83.515,81.382 83.718,81.178 C383_UB1.2@83.718,79.087 ; R274_UB1.2@83.591,19.66 83.591,19.101 85.217,17.475 C294_UB1.2@85.446,17.475 ; C317_UB1.2@86.462,43.129 86.512,43.18 R262_UB1.2@86.512,44.602 v1(88.011,44.602) ; R273_UB1.1@86.487,36.83 86.487,36.043 v1(86.512,36.017) ; C297_UB1.1@86.512,33.68 R276_UB1.1@86.512,35.179 v1(86.512,36.017) ; R273_UB1.1@86.512,36.83 v1(86.512,36.017) ; v2(92.024,19.05) C417_UB1.2@92.024,17.932 93.193,17.932 93.37,17.755 ; C413_UB1.2@92.177,26.492 92.177,27.076 92.837,27.737 U62_UB1.3@95.052,27.737 97.46,27.737 97.536,27.813 ; v2(93.599,31.318) 93.599,30.861 94.183,30.277 U62_UB1.1@95.052,30.277 97.079,30.277 97.536,29.82 97.536,27.813 ; v1(93.701,72.613) 94.925,72.613 C385_UB1.2@95.225,72.314 ; C418_UB1.2@94.056,15.646 94.056,17.069 C419_UB1.2@94.031,17.094 93.37,17.755 ; U62_UB1.10@95.052,18.847 93.37,18.847 ; U62_UB1.5@95.052,25.197 97.536,25.197 ; v1(100.965,86.69) 100.99,86.665 C318_UB1.2@100.99,85.954 ; R310_UB1.1@117.856,88.621 118.369,88.621 v1@118.928,89.179 ; v2(54.28,40.691) 55.804,40.691 C313_UB1.2@56.159,40.335 ; v2(54.28,40.691) 54.28,40.589 54.534,40.335 C313_UB1.2@56.159,40.335 ; 93.37,17.755 93.37,18.847 ; 93.37,18.847 93.37,19.761 93.726,20.117 U62_UB1.9@95.052,20.117 97.155,20.117 97.536,20.498 97.536,25.197 ; 97.536,25.197 97.536,27.813
  Top Layer w1.016: U39_UB1.9@72.314,27.432 U39_UB1.7@72.314,29.896
  Top Layer w1.27: C263_UB1.2@75.311,13.716 R210_UB1.1@77.47,13.716 v3(78.994,13.716) ; C295_UB1.1@81.661,19.634 R274_UB1.2@83.312,19.634 ; U46_UB1.7@83.668,29.794 83.668,27.33 U46_UB1.9@84.277,26.721 ; 86.385,13.691 86.385,13.868 86.665,14.148 C296_UB1.1@86.665,19.685 ; P4_UB1.4@100.533,99.853 101.377,99.853 103.784,102.26 R1.1@105.334,102.26
  Top Layer w1.524: C255_UB1.2@67.793,43.18 67.793,40.691 C254_UB1.2@67.742,40.64 ; C254_UB1.2@67.843,40.64 C254_UB1.2@67.742,40.64 ; 64.745,37.643 64.745,37.228 UP4_UB1.5@63.262,35.745 63.262,36.16 64.745,37.643 ; 64.745,37.643 C314_UB1.2@64.745,39.319 ; C314_UB1.2@64.745,39.319 66.065,40.64 ; C314_UB1.2@64.745,39.319 64.745,40.615 64.77,40.64 66.065,40.64 ; 66.065,40.64 C254_UB1.2@67.742,40.64
  Top Layer w2.032: v8@65.761,13.818 v8(65.786,13.792) C16_UB1.2@68.453,13.792 C233_UB1.2@72.212,13.792 75.235,13.792 C263_UB1.2@75.311,13.716
  Mid-Layer 1 w0.381: 65.634,69.952 65.824,70.142 67.958,70.142 v1(67.97,70.129)
  Mid-Layer 1 w0.508: v1(36.601,70.51) 36.601,70.077 36.672,70.006 ; 55.931,79.451 56.032,79.35 v1(56.032,78.08) 56.032,77.292 ; 59.106,71.018 59.106,71.145 60.3,72.339 60.3,73.213 60.924,73.838 ; 60.223,73.838 60.924,73.838 ; 60.35,65.938 61.087,66.675 v1(61.747,66.675) ; 60.909,60.198 61.011,60.096 v1(62.56,60.096) 63.906,60.096 ; v1(61.697,73.838) 60.924,73.838 ; 61.976,67.793 61.824,67.64 ; 63.17,70.637 62.408,70.637 61.849,70.079 v1(61.849,69.748) 61.824,69.723 61.824,67.64 ; 65.913,72.314 66.269,72.314 v1@67.234,73.279 ; 66.281,72.801 66.269,72.801 66.747,73.279 v1@67.234,73.279 ; v1(67.97,70.129) 69.647,70.129 69.698,70.079 ; 69.342,73.558 69.113,73.33 v1(67.285,73.33) v1@67.234,73.279 ; 101.448,60.935 101.55,60.832 105.387,60.832 v1(105.918,60.301) ; 107.163,87.325 107.213,87.376 v1(108.255,87.376) ; v1(111.1,81.534) 111.1,80.34 111.125,80.315 ; v1(61.747,66.675) 61.747,67.564 61.824,67.64 ; v1(61.747,66.675) 61.824,66.751 61.824,67.64
  Mid-Layer 1 w0.762: v1(48.158,77.521) 48.158,78.003 48.235,78.08 49.42,78.08 49.911,77.589 49.911,77.546 50.101,77.356 v2(53.442,77.356) ; 112.624,85.75 112.624,85.649 v1(113.36,84.912)
  Mid-Layer 1 w1.524: P2_UB1.4@31.04,79.146 P2_UB1.4@30.836,79.146 30.836,76.429 33.325,73.939 33.325,71.831 36.322,68.834 36.322,68.326
  Mid-Layer 2 w0.254: 83.49,85.877 v1(83.49,86.208)
  Mid-Layer 2 w1.524: 86.335,49.276 86.335,48.664 90.018,44.981 ; 89.713,47.371 90.018,47.066 90.018,44.981 ; v2(93.03,40.665) 92.126,40.665 90.018,42.774 90.018,44.981
  Mid-Layer 4 w1.27: 28.143,69.444 30.734,69.444 32.106,70.815 32.106,75.921 30.836,77.191 P2_UB1.4@30.836,79.146
  Bottom Layer w0.254: 55.016,58.039 v1(55.728,57.328) 56.21,57.81 56.21,57.861 ; R364_UB1.2@56.413,67.132 57.81,67.132 58.268,66.675 v1(61.747,66.675) ; 58.975,57.302 59.025,57.353 v1(59.817,57.353) ; 59.792,58.242 59.817,58.217 v1(59.817,57.353) ; 61.087,57.353 v1(59.817,57.353) ; v1(75.387,76.327) 75.616,76.098 C387_UB1.2@77.165,76.098 ; v1(77.191,68.224) 77.826,67.589 C316_UB1.2@78.664,67.589 ; C391_UB1.1@108.077,84.658 108.077,87.198 v1(108.255,87.376) ; v1(113.36,84.912) v1@113.375,84.898 ; C384_UB1.1@115.595,84.898 115.621,84.872 C390_UB1.1@115.621,83.424
  Bottom Layer w0.381: v1(54.127,85.75) 54.585,85.75 ; RN20_UB1.2@54.578,87.503 54.578,85.757 54.585,85.75 ; RN20_UB1.4@55.378,87.503 55.378,85.884 55.245,85.75 ; RN20_UB1.6@56.178,87.503 56.178,85.922 56.007,85.75 ; RN20_UB1.8@56.979,87.503 56.979,85.909 56.82,85.75 ; RN19_UB1.2@59.074,87.503 59.074,85.795 59.03,85.75 ; RN19_UB1.4@59.874,87.503 59.874,85.782 59.842,85.75 ; RN19_UB1.6@60.674,87.503 60.674,85.757 60.681,85.75 ; v1(62.896,87.02) 62.845,86.97 61.519,86.97 ; 54.585,85.75 55.245,85.75 ; 55.245,85.75 56.007,85.75 ; 56.007,85.75 56.82,85.75 ; 56.82,85.75 59.03,85.75 ; 59.03,85.75 59.842,85.75 ; 59.842,85.75 60.681,85.75 ; 60.681,85.75 61.214,85.75 ; 61.214,85.75 61.474,86.011 61.474,86.97 ; 61.214,85.75 61.519,86.055 61.519,86.97 ; 61.474,86.97 RN19_UB1.8@61.474,87.503 61.519,87.459 61.519,86.97 ; 61.474,86.97 61.519,86.97
  Bottom Layer w0.508: v1(36.601,70.51) 36.601,70.18 36.678,70.104 C336_UB1.1@37.973,70.104 ; C414_UB1.2@91.11,25.578 91.11,26.34 91.338,26.568 93.497,26.568 93.624,26.441 U61_UB1.7@95.001,26.441
  Bottom Layer w0.762: v1@24.257,51.232 C376_UB1.2@25.476,51.232 ; v1(24.282,46.634) C375_UB1.2@25.476,46.634 ; v1@24.359,57.76 C366_UB1.1@25.502,57.76 R302_UB1.1@25.502,59.309 ; v1(36.474,65.684) 36.601,65.557 C349_UB1.1@38.075,65.557 38.1,65.583 C408_UB1.1@38.1,67.031 38.1,69.977 C336_UB1.1@37.973,70.104 ; C10_UB1.2@41.554,57.607 41.834,57.887 41.834,62.052 C401_UB1.2@41.554,62.332 ; v1@42.093,97.663 R27_UB1.1@42.093,98.857 ; C348_UB1.1@43.078,53.772 43.104,53.746 C338_UB1.1@47.346,53.746 ; U60_UB1.4@46.761,68.021 48.26,68.021 48.26,66.802 v1(48.336,66.726) 48.336,67.615 49.657,68.936 49.657,71.349 50.241,71.933 C358_UB1.2@50.241,72.009 51.867,72.009 51.892,71.984 51.892,73.177 51.613,73.457 C339_UB1.1@52.248,74.092 52.984,74.092 53.442,74.549 v2(53.442,77.356) R296_UB1.2@52.07,77.356 ; C237_UB1.1@47.244,105.548 47.295,105.497 47.295,102.098 v2(47.386,102.006) 48.844,102.006 ; C403_UB1.2@47.574,47.777 48.489,47.777 ; v2(48.539,48.87) 48.539,47.828 48.489,47.777 ; C228_UB1.2@48.844,100.686 48.844,102.006 ; U35_UB1.5@49.18,108.636 49.18,102.103 49.276,102.006 ; C404_UB1.2@49.454,47.676 49.352,47.777 48.489,47.777 ; v2(49.733,102.006) 49.276,102.006 ; R241_UB1.1@51.44,102.006 v2(52.654,102.006) ; R254_UB1.1@57.282,102.006 57.308,101.981 v2(58.623,101.981) ; R227_UB1.1@62.896,101.956 v2(64.16,101.956) ; C386_UB1.2@86.055,88.367 v1(87.325,88.367) ; C415_UB1.2@92.126,31.217 92.227,31.318 v2(93.599,31.318) 93.599,30.632 93.98,30.251 U61_UB1.10@95.001,30.251 97.028,30.251 97.561,29.718 97.561,28.931 ; U61_UB1.1@95.001,18.821 96.952,18.821 97.561,19.431 v2(97.561,21.361) ; U61_UB1.3@95.001,21.361 v2(97.561,21.361) ; U61_UB1.7@95.001,26.441 v2(97.497,26.441) v2@97.561,26.377 ; U61_UB1.9@95.001,28.981 97.511,28.981 97.561,28.931 ; C315_UB1.2@101.498,63.652 101.651,63.805 101.651,65.43 101.778,65.557 v1@103.124,65.557 ; C265_UB1.2@108.128,67.335 110.388,67.335 110.566,67.158 ; C266_UB1.1@109.652,61.214 109.677,61.189 110.261,61.189 110.566,61.493 C322_UB1.1@110.566,62.713 C310_UB1.1@110.566,64.313 110.566,67.158 ; 112.751,85.979 112.751,85.522 v1(113.36,84.912) ; v1@113.375,84.898 113.462,84.811 113.944,84.811 ; v1(114.275,68.402) 114.224,68.351 110.947,68.351 110.566,67.97 110.566,67.158 ; C390_UB1.1@115.621,83.424 115.606,83.439 C368_UB1.1@114.173,83.439 114.173,84.582 113.944,84.811 ; v1(118.923,89.256) 118.288,88.621 116.154,88.621 115.595,88.062 C384_UB1.1@115.595,84.898 115.508,84.811 113.944,84.811 ; R299_UB1.1@34.188,68.555 34.265,68.478 34.265,67.843 34.29,67.818 36.119,67.818 v2(36.22,67.92) 36.22,68.555 ; R299_UB1.1@34.188,68.555 34.188,69.063 34.265,69.139 v2(36.195,69.139) 36.195,68.631 36.246,68.58 36.22,68.555 ; R299_UB1.1@34.188,68.555 36.22,68.555 ; 48.844,102.006 49.276,102.006 ; v2(97.561,21.361) v2@97.561,26.377 ; v2@97.561,26.377 97.561,28.931
  Bottom Layer w1.016: C340_UB1.1@51.613,81.128 C340_UB1.1@51.638,81.153 ; v1(51.816,82.55) 51.816,81.331 C340_UB1.1@51.638,81.153 ; v1(63.957,80.67) 63.906,80.721 63.906,80.848 63.602,81.153 C342_UB1.1@60.731,81.153 C341_UB1.1@55.093,81.153 C340_UB1.1@51.638,81.153
  Bottom Layer w1.27: C338_UB1.1@47.346,53.746 C332_UB1.1@59.792,53.746 ; 84.811,28.016 85.115,27.711 v3(85.115,26.695)
  Bottom Layer w2.032: v8(65.786,13.792) 78.918,13.792 v3(78.994,13.716)
  other v1: 75.413,35.941 24.282,51.232 24.308,57.76 72.746,78.858 83.515,88.24 64.77,90.881 42.113,97.663
  other v2: 91.989,39.522 94.021,39.522 92.09,40.64 93.97,40.64 89.713,61.773 27.915,69.139 83.439,81.356
  other v3: 87.681,14.249 87.681,17.399 79.477,26.289 68.326,26.377 83.388,26.695 72.085,26.822 73.762,26.822 79.502,40.767 77.546,41.986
